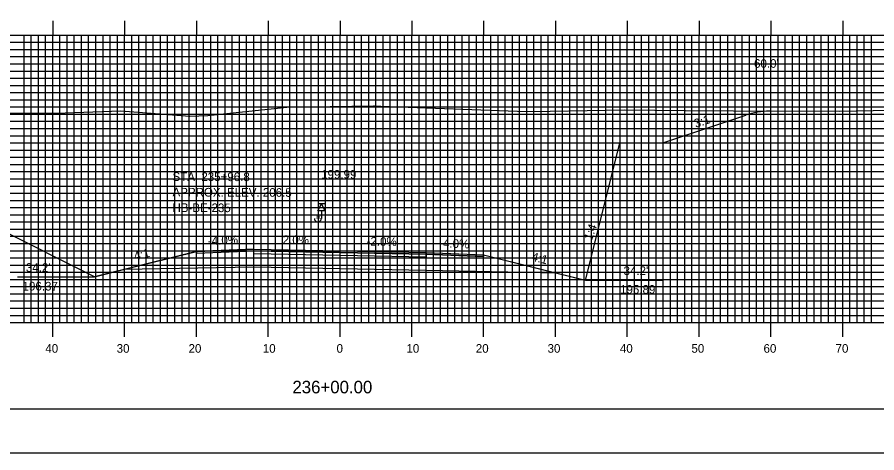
# Model space of a CAD drawing. Extents: x 1800749 to 1801092, y 442591 to 442811.
# Drawn here: x 1800869.6 to 1800989.3, y 442590.5 to 442651.2 of the extents above; entities that cross this region are included whole.
import ezdxf

# ---------------------------------------------------------------- set-up
doc = ezdxf.new("R2010")
doc.units = 0
for name, color, linetype in [('ANNOTATION', 7, 'Continuous'), ('BORDER', 7, 'Continuous'), ('BORING - REFUSAL', 7, 'Continuous'), ('D_Roadway_Centerline', 7, 'Continuous'), ('D_Roadway_Centerline_Text', 7, 'Continuous'), ('D_Roadway_Edge_Shoulder', 7, 'Continuous'), ('D_Roadway_Edge_TW', 7, 'Continuous'), ('D_Roadway_Pavement', 7, 'Continuous'), ('D_Roadway_SlopeLines', 7, 'Continuous'), ('D_Roadway_SubGrade', 7, 'Continuous'), ('D_Text_Standard', 7, 'Continuous'), ('H_V ANNOTATION', 7, 'Continuous'), ('MAJOR', 7, 'Continuous'), ('MINOR', 7, 'Continuous'), ('PDRAIN', 7, 'Continuous'), ('PLOT BOUNDARY', 7, 'Continuous'), ('S_Roadway_Centerline', 7, 'Continuous')]:
    doc.layers.add(name, color=color, linetype=linetype)

msp = doc.modelspace()

# ---------------------------------------------------------------- linework, layer by layer
at = {"layer": 'ANNOTATION'}
msp.add_line((1800948.72, 442614.56), (1800951.36, 442625.08), dxfattribs=at)
at = {"layer": 'BORDER'}
msp.add_lwpolyline([(1800764.95, 442596.67), (1801084.95, 442596.67), (1801084.95, 442806.67), (1800764.95, 442806.67)], close=True, dxfattribs=at)
at = {"layer": 'BORING - REFUSAL'}
for p, q in [((1800912.43, 442625.17), (1800911.47, 442625.17)), ((1800911.95, 442624.21), (1800911.95, 442623.15))]:
    msp.add_line(p, q, dxfattribs=at)
msp.add_lwpolyline([(1800911.95, 442625.17), (1800912.43, 442624.21), (1800911.47, 442624.21)], close=True, dxfattribs=at)
msp.add_arc((1800911.46, 442623.15), 0.485, 180, 0, dxfattribs=at)
at = {"layer": 'D_Roadway_Centerline'}
msp.add_lwpolyline([(1800880.38, 442615.04), (1800884.38, 442616.04), (1800894.55, 442618.58), (1800902.55, 442618.9), (1800914.55, 442618.66), (1800926.55, 442618.42), (1800934.55, 442618.1), (1800944.72, 442615.56), (1800948.72, 442614.56)], dxfattribs=at)
at = {"layer": 'D_Roadway_Edge_Shoulder'}
for points in [[(1800902.55, 442618.9), (1800894.55, 442618.58), (1800894.55, 442618.33), (1800902.55, 442618.65)], [(1800926.55, 442618.42), (1800934.55, 442618.1), (1800934.55, 442617.85), (1800926.55, 442618.17)]]:
    msp.add_lwpolyline(points, close=True, dxfattribs=at)
at = {"layer": 'D_Roadway_Edge_TW'}
msp.add_lwpolyline([(1800902.55, 442618.65), (1800902.55, 442618.9), (1800914.55, 442618.66), (1800926.55, 442618.42), (1800926.55, 442618.17), (1800914.55, 442618.41)], close=True, dxfattribs=at)
at = {"layer": 'D_Roadway_Pavement'}
msp.add_lwpolyline([(1800902.55, 442618.23), (1800902.55, 442618.65), (1800914.55, 442618.41), (1800926.55, 442618.17), (1800926.55, 442617.75), (1800914.55, 442617.99)], close=True, dxfattribs=at)
at = {"layer": 'D_Roadway_SlopeLines'}
for p, q in [((1800959.5, 442633.67), (1800971.05, 442637.52)), ((1800880.38, 442615.04), (1800837.81, 442636.32))]:
    msp.add_line(p, q, dxfattribs=at)
for points in [[(1800951.36, 442625.08), (1800953.5, 442633.67), (1800959.5, 442633.67)], [(1800894.55, 442618.58), (1800880.38, 442615.04)], [(1800934.55, 442618.1), (1800948.72, 442614.56)]]:
    msp.add_lwpolyline(points, dxfattribs=at)
msp.add_arc((1800974.71, 442626.53), 11.58, 91.6389, 108.4349, dxfattribs=at)
at = {"layer": 'D_Roadway_SubGrade'}
msp.add_lwpolyline([(1800902.55, 442616.4), (1800884.38, 442616.04), (1800894.55, 442618.58), (1800894.55, 442618.33), (1800902.55, 442618.65), (1800914.55, 442618.41), (1800926.55, 442618.17), (1800934.55, 442617.85), (1800934.55, 442618.1), (1800944.72, 442615.56), (1800926.55, 442615.92), (1800914.55, 442616.16)], close=True, dxfattribs=at)
at = {"layer": 'MAJOR'}
for p, q in [((1800874.55, 442650.67), (1800874.55, 442648.67)), ((1800884.55, 442650.67), (1800884.55, 442648.67)), ((1800894.55, 442650.67), (1800894.55, 442648.67)), ((1800904.55, 442650.67), (1800904.55, 442648.67)), ((1800914.55, 442650.67), (1800914.55, 442648.67)), ((1800924.55, 442650.67), (1800924.55, 442648.67)), ((1800934.55, 442650.67), (1800934.55, 442648.67)), ((1800944.55, 442650.67), (1800944.55, 442648.67)), ((1800954.55, 442650.67), (1800954.55, 442648.67)), ((1800964.55, 442650.67), (1800964.55, 442648.67)), ((1800974.55, 442650.67), (1800974.55, 442648.67)), ((1800984.55, 442650.67), (1800984.55, 442648.67)), ((1800774.55, 442648.67), (1801054.55, 442648.67)), ((1800774.55, 442648.67), (1801054.55, 442648.67)), ((1800874.55, 442608.67), (1800874.55, 442648.67)), ((1800884.55, 442608.67), (1800884.55, 442648.67)), ((1800894.55, 442608.67), (1800894.55, 442648.67)), ((1800904.55, 442608.67), (1800904.55, 442648.67)), ((1800914.55, 442608.67), (1800914.55, 442648.67)), ((1800924.55, 442608.67), (1800924.55, 442648.67)), ((1800934.55, 442608.67), (1800934.55, 442648.67)), ((1800944.55, 442608.67), (1800944.55, 442648.67)), ((1800954.55, 442608.67), (1800954.55, 442648.67)), ((1800964.55, 442608.67), (1800964.55, 442648.67)), ((1800974.55, 442608.67), (1800974.55, 442648.67)), ((1800984.55, 442608.67), (1800984.55, 442648.67)), ((1800774.55, 442643.67), (1801054.55, 442643.67)), ((1800774.55, 442638.67), (1801054.55, 442638.67)), ((1800774.55, 442633.67), (1801054.55, 442633.67)), ((1800774.55, 442628.67), (1801054.55, 442628.67)), ((1800774.55, 442623.67), (1801054.55, 442623.67)), ((1800774.55, 442618.67), (1801054.55, 442618.67)), ((1800774.55, 442613.67), (1801054.55, 442613.67)), ((1800774.55, 442608.67), (1801054.55, 442608.67)), ((1800774.55, 442608.67), (1801054.55, 442608.67)), ((1800874.55, 442606.66), (1800874.55, 442608.67)), ((1800884.55, 442606.66), (1800884.55, 442608.67)), ((1800894.55, 442606.66), (1800894.55, 442608.67)), ((1800904.55, 442606.66), (1800904.55, 442608.67)), ((1800914.55, 442606.66), (1800914.55, 442608.67)), ((1800924.55, 442606.66), (1800924.55, 442608.67)), ((1800934.55, 442606.66), (1800934.55, 442608.67)), ((1800944.55, 442606.66), (1800944.55, 442608.67)), ((1800954.55, 442606.66), (1800954.55, 442608.67)), ((1800964.55, 442606.66), (1800964.55, 442608.67)), ((1800974.55, 442606.66), (1800974.55, 442608.67)), ((1800984.55, 442606.66), (1800984.55, 442608.67))]:
    msp.add_line(p, q, dxfattribs=at)
at = {"layer": 'MINOR'}
for p, q in [((1800870.55, 442608.67), (1800870.55, 442648.67)), ((1800871.55, 442608.67), (1800871.55, 442648.67)), ((1800872.55, 442608.67), (1800872.55, 442648.67)), ((1800873.55, 442608.67), (1800873.55, 442648.67)), ((1800875.55, 442608.67), (1800875.55, 442648.67)), ((1800876.55, 442608.67), (1800876.55, 442648.67)), ((1800877.55, 442608.67), (1800877.55, 442648.67)), ((1800878.55, 442608.67), (1800878.55, 442648.67)), ((1800879.55, 442608.67), (1800879.55, 442648.67)), ((1800880.55, 442608.67), (1800880.55, 442648.67)), ((1800881.55, 442608.67), (1800881.55, 442648.67)), ((1800882.55, 442608.67), (1800882.55, 442648.67)), ((1800883.55, 442608.67), (1800883.55, 442648.67)), ((1800885.55, 442608.67), (1800885.55, 442648.67)), ((1800886.55, 442608.67), (1800886.55, 442648.67)), ((1800887.55, 442608.67), (1800887.55, 442648.67)), ((1800888.55, 442608.67), (1800888.55, 442648.67)), ((1800889.55, 442608.67), (1800889.55, 442648.67)), ((1800890.55, 442608.67), (1800890.55, 442648.67)), ((1800891.55, 442608.67), (1800891.55, 442648.67)), ((1800892.55, 442608.67), (1800892.55, 442648.67)), ((1800893.55, 442608.67), (1800893.55, 442648.67)), ((1800895.55, 442608.67), (1800895.55, 442648.67)), ((1800896.55, 442608.67), (1800896.55, 442648.67)), ((1800897.55, 442608.67), (1800897.55, 442648.67)), ((1800898.55, 442608.67), (1800898.55, 442648.67)), ((1800899.55, 442608.67), (1800899.55, 442648.67)), ((1800900.55, 442608.67), (1800900.55, 442648.67)), ((1800901.55, 442608.67), (1800901.55, 442648.67)), ((1800902.55, 442608.67), (1800902.55, 442648.67)), ((1800903.55, 442608.67), (1800903.55, 442648.67)), ((1800905.55, 442608.67), (1800905.55, 442648.67)), ((1800906.55, 442608.67), (1800906.55, 442648.67)), ((1800907.55, 442608.67), (1800907.55, 442648.67)), ((1800908.55, 442608.67), (1800908.55, 442648.67)), ((1800909.55, 442608.67), (1800909.55, 442648.67)), ((1800910.55, 442608.67), (1800910.55, 442648.67)), ((1800911.55, 442608.67), (1800911.55, 442648.67)), ((1800912.55, 442608.67), (1800912.55, 442648.67)), ((1800913.55, 442608.67), (1800913.55, 442648.67)), ((1800915.55, 442608.67), (1800915.55, 442648.67)), ((1800916.55, 442608.67), (1800916.55, 442648.67)), ((1800917.55, 442608.67), (1800917.55, 442648.67)), ((1800918.55, 442608.67), (1800918.55, 442648.67)), ((1800919.55, 442608.67), (1800919.55, 442648.67)), ((1800920.55, 442608.67), (1800920.55, 442648.67)), ((1800921.55, 442608.67), (1800921.55, 442648.67)), ((1800922.55, 442608.67), (1800922.55, 442648.67)), ((1800923.55, 442608.67), (1800923.55, 442648.67)), ((1800925.55, 442608.67), (1800925.55, 442648.67)), ((1800926.55, 442608.67), (1800926.55, 442648.67)), ((1800927.55, 442608.67), (1800927.55, 442648.67)), ((1800928.55, 442608.67), (1800928.55, 442648.67)), ((1800929.55, 442608.67), (1800929.55, 442648.67)), ((1800930.55, 442608.67), (1800930.55, 442648.67)), ((1800931.55, 442608.67), (1800931.55, 442648.67)), ((1800932.55, 442608.67), (1800932.55, 442648.67)), ((1800933.55, 442608.67), (1800933.55, 442648.67)), ((1800935.55, 442608.67), (1800935.55, 442648.67)), ((1800936.55, 442608.67), (1800936.55, 442648.67)), ((1800937.55, 442608.67), (1800937.55, 442648.67)), ((1800938.55, 442608.67), (1800938.55, 442648.67)), ((1800939.55, 442608.67), (1800939.55, 442648.67)), ((1800940.55, 442608.67), (1800940.55, 442648.67)), ((1800941.55, 442608.67), (1800941.55, 442648.67)), ((1800942.55, 442608.67), (1800942.55, 442648.67)), ((1800943.55, 442608.67), (1800943.55, 442648.67)), ((1800945.55, 442608.67), (1800945.55, 442648.67)), ((1800946.55, 442608.67), (1800946.55, 442648.67)), ((1800947.55, 442608.67), (1800947.55, 442648.67)), ((1800948.55, 442608.67), (1800948.55, 442648.67)), ((1800949.55, 442608.67), (1800949.55, 442648.67)), ((1800950.55, 442608.67), (1800950.55, 442648.67)), ((1800951.55, 442608.67), (1800951.55, 442648.67)), ((1800952.55, 442608.67), (1800952.55, 442648.67)), ((1800953.55, 442608.67), (1800953.55, 442648.67)), ((1800955.55, 442608.67), (1800955.55, 442648.67)), ((1800956.55, 442608.67), (1800956.55, 442648.67)), ((1800957.55, 442608.67), (1800957.55, 442648.67)), ((1800958.55, 442608.67), (1800958.55, 442648.67)), ((1800959.55, 442608.67), (1800959.55, 442648.67)), ((1800960.55, 442608.67), (1800960.55, 442648.67)), ((1800961.55, 442608.67), (1800961.55, 442648.67)), ((1800962.55, 442608.67), (1800962.55, 442648.67)), ((1800963.55, 442608.67), (1800963.55, 442648.67)), ((1800965.55, 442608.67), (1800965.55, 442648.67)), ((1800966.55, 442608.67), (1800966.55, 442648.67)), ((1800967.55, 442608.67), (1800967.55, 442648.67)), ((1800968.55, 442608.67), (1800968.55, 442648.67)), ((1800969.55, 442608.67), (1800969.55, 442648.67)), ((1800970.55, 442608.67), (1800970.55, 442648.67)), ((1800971.55, 442608.67), (1800971.55, 442648.67)), ((1800972.55, 442608.67), (1800972.55, 442648.67)), ((1800973.55, 442608.67), (1800973.55, 442648.67)), ((1800975.55, 442608.67), (1800975.55, 442648.67)), ((1800976.55, 442608.67), (1800976.55, 442648.67)), ((1800977.55, 442608.67), (1800977.55, 442648.67)), ((1800978.55, 442608.67), (1800978.55, 442648.67)), ((1800979.55, 442608.67), (1800979.55, 442648.67)), ((1800980.55, 442608.67), (1800980.55, 442648.67)), ((1800981.55, 442608.67), (1800981.55, 442648.67)), ((1800982.55, 442608.67), (1800982.55, 442648.67)), ((1800983.55, 442608.67), (1800983.55, 442648.67)), ((1800985.55, 442608.67), (1800985.55, 442648.67)), ((1800986.55, 442608.67), (1800986.55, 442648.67)), ((1800987.55, 442608.67), (1800987.55, 442648.67)), ((1800988.55, 442608.67), (1800988.55, 442648.67)), ((1800774.55, 442647.67), (1801054.55, 442647.67)), ((1800774.55, 442646.67), (1801054.55, 442646.67)), ((1800774.55, 442645.67), (1801054.55, 442645.67)), ((1800774.55, 442644.67), (1801054.55, 442644.67)), ((1800774.55, 442642.67), (1801054.55, 442642.67)), ((1800774.55, 442641.67), (1801054.55, 442641.67)), ((1800774.55, 442640.67), (1801054.55, 442640.67)), ((1800774.55, 442639.67), (1801054.55, 442639.67)), ((1800774.55, 442637.67), (1801054.55, 442637.67)), ((1800774.55, 442636.67), (1801054.55, 442636.67)), ((1800774.55, 442635.67), (1801054.55, 442635.67)), ((1800774.55, 442634.67), (1801054.55, 442634.67)), ((1800774.55, 442632.67), (1801054.55, 442632.67)), ((1800774.55, 442631.67), (1801054.55, 442631.67)), ((1800774.55, 442630.67), (1801054.55, 442630.67)), ((1800774.55, 442629.67), (1801054.55, 442629.67)), ((1800774.55, 442627.67), (1801054.55, 442627.67)), ((1800774.55, 442626.67), (1801054.55, 442626.67)), ((1800774.55, 442625.67), (1801054.55, 442625.67)), ((1800774.55, 442624.67), (1801054.55, 442624.67)), ((1800774.55, 442622.67), (1801054.55, 442622.67)), ((1800774.55, 442621.67), (1801054.55, 442621.67)), ((1800774.55, 442620.67), (1801054.55, 442620.67)), ((1800774.55, 442619.67), (1801054.55, 442619.67)), ((1800774.55, 442617.67), (1801054.55, 442617.67)), ((1800774.55, 442616.67), (1801054.55, 442616.67)), ((1800774.55, 442615.67), (1801054.55, 442615.67)), ((1800774.55, 442614.67), (1801054.55, 442614.67)), ((1800774.55, 442612.67), (1801054.55, 442612.67)), ((1800774.55, 442611.67), (1801054.55, 442611.67)), ((1800774.55, 442610.67), (1801054.55, 442610.67)), ((1800774.55, 442609.67), (1801054.55, 442609.67))]:
    msp.add_line(p, q, dxfattribs=at)
at = {"layer": 'PDRAIN'}
for p, q in [((1800869.65, 442615.04), (1800880.38, 442615.04)), ((1800948.72, 442614.56), (1800959.49, 442614.56))]:
    msp.add_line(p, q, dxfattribs=at)
at = {"layer": 'PLOT BOUNDARY'}
msp.add_lwpolyline([(1800748.76, 442590.55), (1801088.76, 442590.55), (1801088.76, 442810.55), (1800748.76, 442810.55)], close=True, dxfattribs=at)
at = {"layer": 'S_Roadway_Centerline'}
msp.add_lwpolyline([(1800868.26, 442637.83), (1800871.95, 442637.79), (1800874.99, 442637.82), (1800884.01, 442638.14), (1800893.63, 442637.4), (1800896.16, 442637.48), (1800907.13, 442638.64), (1800919.19, 442638.81), (1800919.27, 442638.81), (1800919.34, 442638.81), (1800920.25, 442638.78), (1800940.51, 442638.05), (1800943.79, 442638.08), (1800954.1, 442638.27), (1800962.65, 442638.16), (1800969.33, 442638.11), (1800984.04, 442638.09), (1800993.51, 442638.26)], dxfattribs=at)

# ---------------------------------------------------------------- texts
at = {"layer": 'ANNOTATION'}
for s, rotation, p in [('3:1', 18.4349, (1800964.08, 442635.75)), ('3:1', 18.4349, (1800964.08, 442635.75)), ('1:4', 70.516, (1800949.61, 442620.02)), ('-4.0%', 2.2906, (1800896.18, 442619.45)), ('2.0%', 358.8542, (1800906.56, 442619.62)), ('-2.0%', 358.8542, (1800918.24, 442619.39)), ('-4.0%', 357.7094, (1800928.34, 442619.15)), ('4:1', 14.0362, (1800886, 442617.3)), ('4:1', 345.9638, (1800941.14, 442617.31))]:
    msp.add_text(s, height=1.2, rotation=rotation, dxfattribs=at).set_placement(p)
for s, p in [("34.2'", (1800870.81, 442615.73)), ("34.2'", (1800954.03, 442615.28)), ('196.37', (1800870.35, 442613.13)), ('195.89', (1800953.55, 442612.68))]:
    msp.add_text(s, height=1.2, dxfattribs=at).set_placement(p)
at = {"layer": 'BORING - REFUSAL'}
for s, p in [('STA. 235+96.8', (1800891.23, 442628.38)), ('APPROX. ELEV. 206.5', (1800891.23, 442626.22)), ('HB-BE-235', (1800891.22, 442624.06))]:
    msp.add_text(s, height=1.2, rotation=359.8142, dxfattribs=at).set_placement(p)
msp.add_text('R', height=0.64, dxfattribs=at).set_placement((1800911.24, 442623.09))
at = {"layer": 'D_Roadway_Centerline'}
for s, p in [('C', (1800914.54, 442618.66)), ('L', (1800914.55, 442618.65))]:
    msp.add_text(s, height=0.0146, dxfattribs=at).set_placement(p)
at = {"layer": 'D_Roadway_Centerline_Text'}
msp.add_text('199.99', height=1.2, dxfattribs=at).set_placement((1800911.92, 442628.69))
at = {"layer": 'D_Text_Standard'}
msp.add_text("60.0'", height=1.2, dxfattribs=at).set_placement((1800972.2, 442644.12))
at = {"layer": 'H_V ANNOTATION'}
for s, height, p in [('40', 1.2, (1800873.52, 442604.47)), ('30', 1.2, (1800883.45, 442604.47)), ('20', 1.2, (1800893.46, 442604.47)), ('10', 1.2, (1800903.8, 442604.47)), ('0', 1.2, (1800914.07, 442604.47)), ('10', 1.2, (1800923.8, 442604.47)), ('20', 1.2, (1800933.46, 442604.47)), ('30', 1.2, (1800943.45, 442604.47)), ('40', 1.2, (1800953.52, 442604.47)), ('50', 1.2, (1800963.48, 442604.47)), ('60', 1.2, (1800973.52, 442604.47)), ('70', 1.2, (1800983.55, 442604.47)), ('236+00.00', 1.75, (1800907.92, 442598.82))]:
    msp.add_text(s, height=height, dxfattribs=at).set_placement(p)

doc.saveas('drawing.dxf')
